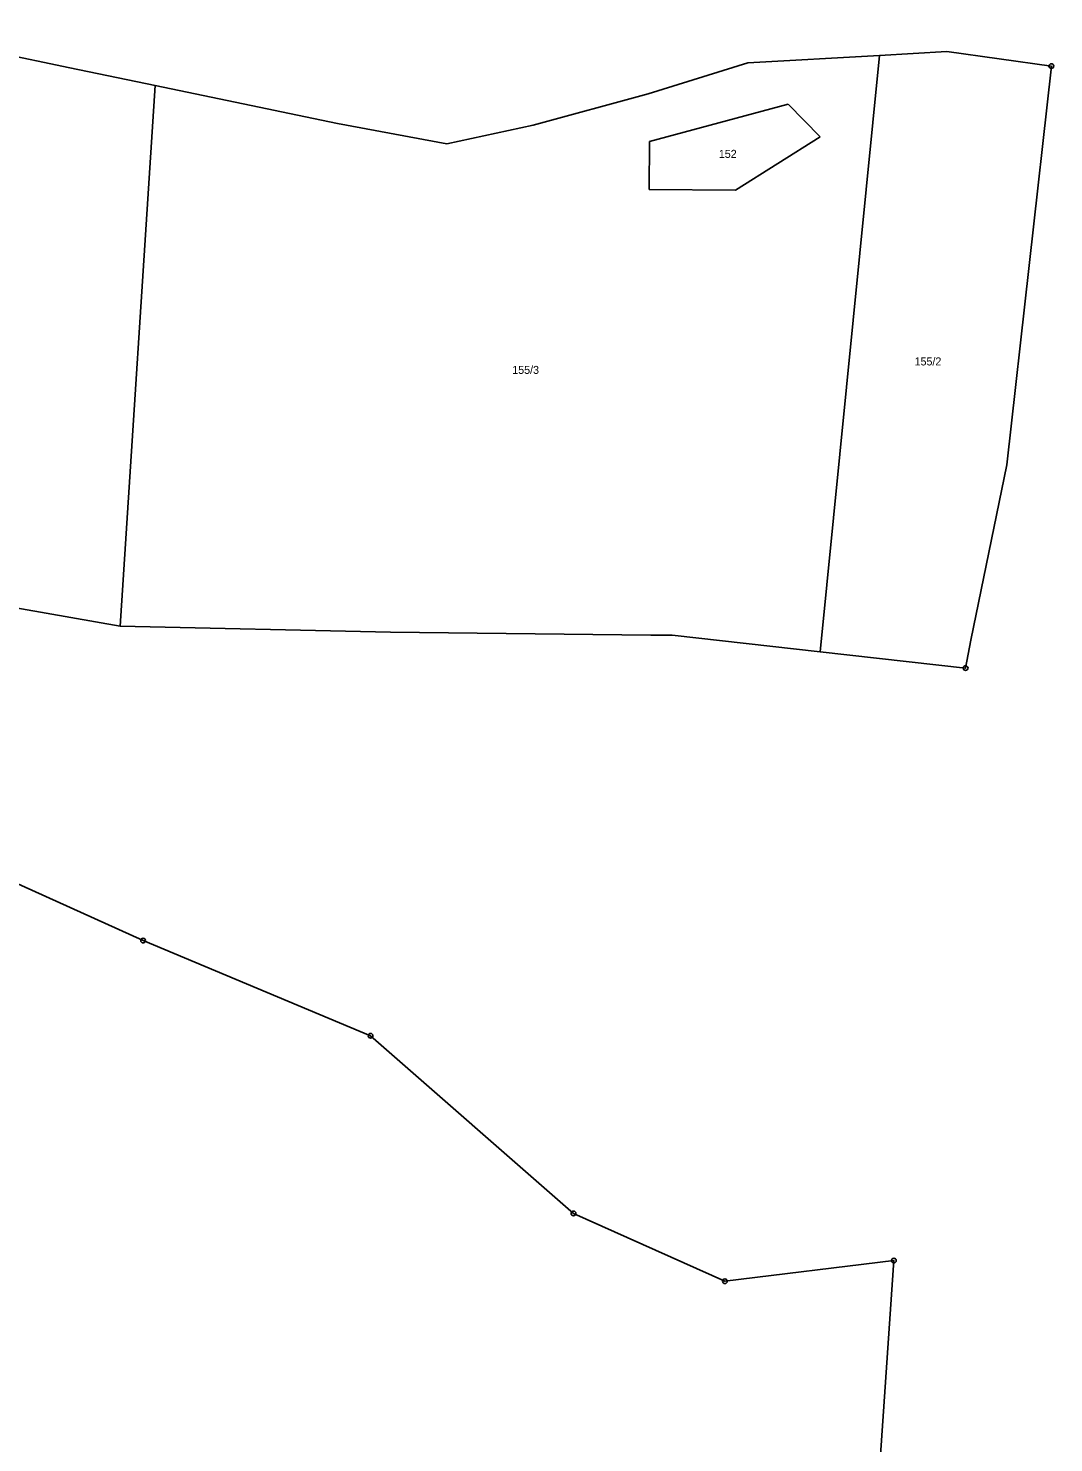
# Model space of a CAD drawing. Extents: x -794421 to -792735, y -1117671 to -1115559.
# Drawn here: x -793190.4 to -792972.7, y -1116417 to -1116116.6 of the extents above; entities that cross this region are included whole.
import ezdxf

# ---------------------------------------------------------------- set-up
doc = ezdxf.new("R2010")
doc.units = 0
for name, color, linetype in [('Vrstva 1', 7, 'Continuous'), ('Vrstva 14', 7, 'Continuous'), ('Vrstva 28', 7, 'Continuous'), ('Vrstva 3', 7, 'Continuous')]:
    doc.layers.add(name, color=color, linetype=linetype)

msp = doc.modelspace()

# ---------------------------------------------------------------- linework, layer by layer
at = {"layer": 'Vrstva 1'}
for p, q in [((-793009.71, -1116122.37), (-793022.31, -1116249.03)), ((-793170.87, -1116243.6), (-793163.48, -1116128.74)), ((-793058.54, -1116140.65), (-793029.09, -1116132.71)), ((-793029.09, -1116132.71), (-793022.27, -1116139.69)), ((-793058.59, -1116150.86), (-793058.54, -1116140.65)), ((-793022.27, -1116139.69), (-793040.25, -1116151.01)), ((-793040.25, -1116151.01), (-793058.59, -1116150.86))]:
    msp.add_line(p, q, dxfattribs=at)
at = {"layer": 'Vrstva 28'}
for centre, radius in [((-792973.22, -1116124.65), 0.5), ((-792973.22, -1116124.65), 0.01), ((-792991.41, -1116252.48), 0.5), ((-792991.41, -1116252.48), 0.01), ((-793166.01, -1116310.36), 0.5), ((-793166.01, -1116310.36), 0.01), ((-793117.72, -1116330.58), 0.5), ((-793117.72, -1116330.58), 0.01), ((-793074.65, -1116368.31), 0.5), ((-793074.65, -1116368.31), 0.01), ((-793006.64, -1116378.31), 0.5), ((-793006.64, -1116378.31), 0.01), ((-793042.52, -1116382.7), 0.5), ((-793042.52, -1116382.7), 0.01)]:
    msp.add_circle(centre, radius, dxfattribs=at)
at = {"layer": 'Vrstva 3'}
for p, q in [((-793181.58, -1116125), (-793221.43, -1116116.61)), ((-793037.62, -1116123.95), (-793009.71, -1116122.37)), ((-793009.71, -1116122.37), (-792995.43, -1116121.56)), ((-792995.43, -1116121.56), (-792973.22, -1116124.65)), ((-793181.58, -1116125), (-793163.48, -1116128.74)), ((-793058.79, -1116130.54), (-793037.62, -1116123.95)), ((-792973.22, -1116124.65), (-792982.68, -1116209.32)), ((-793163.48, -1116128.74), (-793151.53, -1116131.21)), ((-793151.53, -1116131.21), (-793124.75, -1116136.82)), ((-793083.22, -1116137.2), (-793058.79, -1116130.54)), ((-793124.75, -1116136.82), (-793101.56, -1116141.15)), ((-793101.56, -1116141.15), (-793083.22, -1116137.2)), ((-792982.68, -1116209.32), (-792990.29, -1116246.55)), ((-793204.36, -1116237.71), (-793170.87, -1116243.6)), ((-793170.87, -1116243.6), (-793113.52, -1116244.86)), ((-793113.52, -1116244.86), (-793058.22, -1116245.53)), ((-793058.22, -1116245.53), (-793053.7, -1116245.53)), ((-793053.7, -1116245.53), (-793022.31, -1116249.03)), ((-792990.29, -1116246.55), (-792991.41, -1116252.48)), ((-793022.31, -1116249.03), (-792991.41, -1116252.48)), ((-793166.01, -1116310.36), (-793223.68, -1116284.29)), ((-793117.72, -1116330.58), (-793166.01, -1116310.36)), ((-793074.65, -1116368.31), (-793117.72, -1116330.58)), ((-793042.52, -1116382.7), (-793074.65, -1116368.31)), ((-793006.64, -1116378.31), (-793042.52, -1116382.7)), ((-793012.18, -1116458.29), (-793006.64, -1116378.31))]:
    msp.add_line(p, q, dxfattribs=at)

# ---------------------------------------------------------------- texts
at = {"layer": 'Vrstva 14'}
for s, p in [('152', (-793043.806, -1116144.13)), ('155/2', (-793002.256, -1116188.21)), ('155/3', (-793087.656, -1116190.01))]:
    msp.add_text(s, height=1.7, dxfattribs=at).set_placement(p)

doc.saveas('drawing.dxf')
